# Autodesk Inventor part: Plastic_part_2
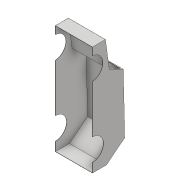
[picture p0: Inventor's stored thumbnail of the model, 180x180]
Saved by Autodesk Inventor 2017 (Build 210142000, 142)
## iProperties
Created: 2016-09
Part Number: Plastic_part_2
Material: Generic
Document SubType Name: Modeling
Designer: Gaurav
Density: 1 g/cm^3
Appearance: Default
Author: Gaurav
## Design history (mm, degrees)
sketch "Sketch1"
  geometry: L1 (0, 430.114)-(156.481, 430.114); L2 (156.481, 430.114)-(201.389, 99.43); L3 (201.389, 99.43)-(371.554, 12.048); L4 (371.554, 12.048)-(387.865, -710.668); L5 (387.865, -710.668)-(168.372, -883.73); L6 (168.372, -883.73)-(0, -883.73); L7 (0, 430.114)-(0, 337.322); L8 (0, 68.93)-(0, -507.615); L9 (0, -775.301)-(0, -883.73); A1 r 133.843 centre (0, -641.458) between (0, -775.301) and (0, -507.615); A2 r 134.422 centre (-7.791, 203.126) between (0, 68.93) and (0, 337.322); 3 further points
  constraints: 18 end point, 4 point on circle, 2 centre point, 2 midpoint, 1 collinear, 1 horizontal, 1 parallel, 1 point on line, 1 vertical, 1 vertical alignment
extrude "Extrusion1" new body sketch "Sketch1" distance "d0" = 446.5; taper "d1" = 0 deg
shell "Shell1" dims "d2" = 3
sketch "Sketch2"
  geometry: L1 (18.992, 168.803)-(427.508, 168.803); L2 (427.508, 168.803)-(427.508, 20.626); L3 (427.508, 20.626)-(18.992, 20.626); L4 (18.992, 20.626)-(18.992, 168.803); L5 (18.992, 168.803)-(427.508, 20.626); L6 (427.508, 168.803)-(18.992, 20.626); 2 further points
  constraints: 12 end point, 2 midpoint, 2 parallel, 1 horizontal, 1 perpendicular
extrude "Extrusion2" cut sketch "Sketch2" stored distance "d3" = 446.5; taper "d4" = 0 deg
body "Solid1"
